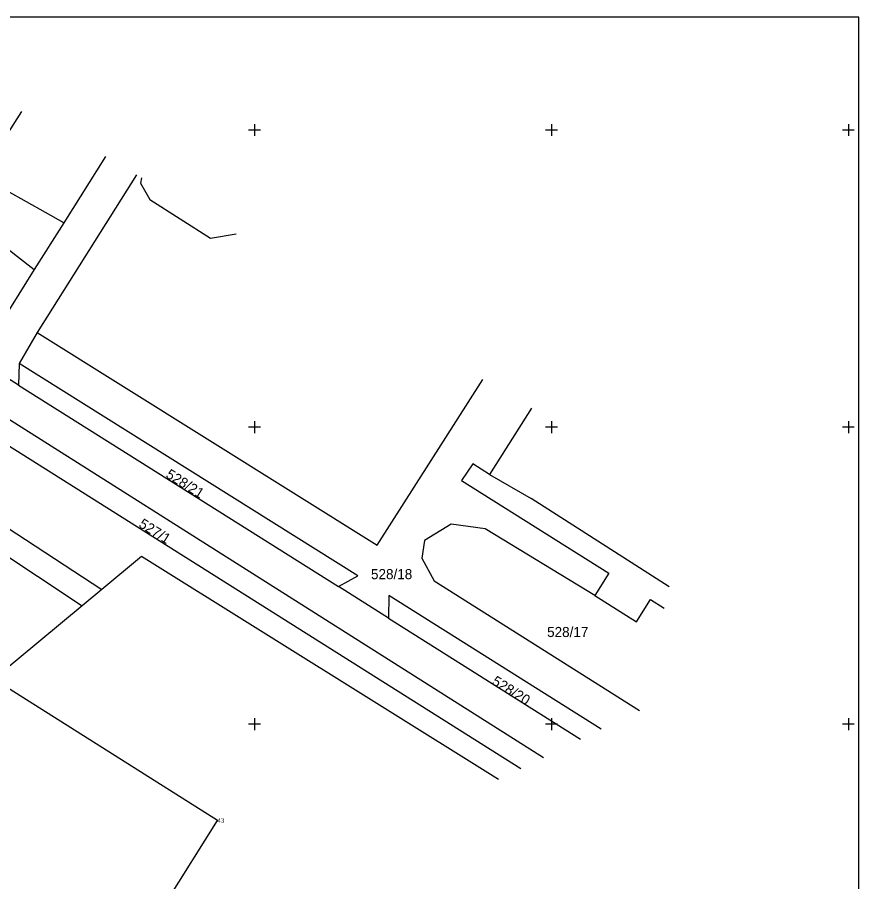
# Model space of a CAD drawing. Extents: x -645398 to -644998, y -1063322 to -1063031.
# Drawn here: x -645140 to -644998.3, y -1063176.5 to -1063031 of the extents above; entities that cross this region are included whole.
import ezdxf

# ---------------------------------------------------------------- set-up
doc = ezdxf.new("R2010")
doc.units = 0
for name, color, linetype in [('Bod', 7, 'Continuous'), ('Hranice KN pozemků', 7, 'Continuous'), ('Rámeček', 7, 'Continuous'), ('Souřadnicové křížky', 7, 'Continuous'), ('Stavby', 7, 'Continuous'), ('Vnitřní kresba parcel', 7, 'Continuous'), ('Čísla parcel', 7, 'Continuous'), ('Číslo bodu', 7, 'Continuous')]:
    doc.layers.add(name, color=color, linetype=linetype)

msp = doc.modelspace()

# ---------------------------------------------------------------- linework, layer by layer
at = {"layer": 'Bod'}
for q in [(-645106.29, -1063166.18), (-645106.29, -1063166.28), (-645106.19, -1063166.18), (-645106.19, -1063166.28)]:
    msp.add_line((-645106.24, -1063166.23), q, dxfattribs=at)
at = {"layer": 'Hranice KN pozemků'}
for p, q in [((-645146.11, -1063057.77), (-645139.21, -1063046.87)), ((-645119.88, -1063057.56), (-645136.61, -1063084.06)), ((-645136.61, -1063084.06), (-645139.63, -1063089.31)), ((-645139.74, -1063092.95), (-645148.3, -1063087.54)), ((-645139.63, -1063089.31), (-645139.74, -1063092.95)), ((-645139.74, -1063092.95), (-645085.88, -1063126.81)), ((-645119.02, -1063121.76), (-645125.74, -1063127.34)), ((-645058.94, -1063159.31), (-645119.02, -1063121.76)), ((-645125.74, -1063127.34), (-645129.04, -1063130.08)), ((-645077.42, -1063132.14), (-645085.88, -1063126.81)), ((-645129.04, -1063130.08), (-645143.96, -1063142.46)), ((-645077.42, -1063132.14), (-645045.1, -1063152.55))]:
    msp.add_line(p, q, dxfattribs=at)
for points in [[(-645236.73, -1063042.91), (-645233.9, -1063041.56), (-645230.85, -1063042.43), (-645219.03, -1063050.07), (-645152.72, -1063091.57), (-645140.39, -1063099.29), (-645051.35, -1063155.61)], [(-645236.73, -1063042.91), (-645154.72, -1063094.74), (-645140.39, -1063103.8), (-645055.15, -1063157.46)], [(-645125.1, -1063054.47), (-645132.12, -1063065.61), (-645135.23, -1063063.87), (-645141.6, -1063060.3), (-645146.11, -1063057.77)], [(-645119.05, -1063058.04), (-645119.23, -1063058.92), (-645117.65, -1063061.72)], [(-645117.65, -1063061.72), (-645107.4, -1063068.19), (-645103.09, -1063067.46)], [(-645149.78, -1063063.57), (-645139.91, -1063071.29), (-645137.09, -1063073.49), (-645144.94, -1063085.95), (-645148.3, -1063087.54)], [(-645136.61, -1063084.06), (-645079.35, -1063119.88), (-645061.53, -1063091.99)], [(-645085.88, -1063126.81), (-645082.63, -1063125.02), (-645139.63, -1063089.31)], [(-645053.34, -1063096.82), (-645060.41, -1063107.97), (-645063.26, -1063106.18), (-645065.12, -1063108.99), (-645040.36, -1063124.59), (-645042.69, -1063128.37)], [(-645186.47, -1063109.12), (-645179.53, -1063104.51), (-645170.44, -1063102.69), (-645159.02, -1063110.24), (-645129.04, -1063130.08)], [(-645042.69, -1063128.37), (-645061.17, -1063117.13), (-645066.86, -1063116.35), (-645071.4, -1063119.09), (-645071.84, -1063122.06), (-645069.75, -1063125.89)], [(-645069.75, -1063125.89), (-645035.16, -1063147.7)], [(-645041.62, -1063150.85), (-645077.39, -1063128.37), (-645077.42, -1063132.14)], [(-645042.69, -1063128.37), (-645035.7, -1063132.76), (-645033.33, -1063129), (-645031, -1063130.48)]]:
    msp.add_lwpolyline(points, dxfattribs=at)
at = {"layer": 'Rámeček'}
for p, q in [((-644998.25, -1063031.02), (-645398.25, -1063031.02)), ((-644998.25, -1063322.02), (-644998.25, -1063031.02))]:
    msp.add_line(p, q, dxfattribs=at)
at = {"layer": 'Souřadnicové křížky'}
for p, q in [((-645100, -1063049), (-645100, -1063051)), ((-645050, -1063049), (-645050, -1063051)), ((-645000, -1063049), (-645000, -1063051)), ((-645099, -1063050), (-645101, -1063050)), ((-645049, -1063050), (-645051, -1063050)), ((-644999, -1063050), (-645001, -1063050)), ((-645099, -1063100), (-645101, -1063100)), ((-645100, -1063099), (-645100, -1063101)), ((-645049, -1063100), (-645051, -1063100)), ((-645050, -1063099), (-645050, -1063101)), ((-644999, -1063100), (-645001, -1063100)), ((-645000, -1063099), (-645000, -1063101)), ((-645100, -1063149), (-645100, -1063151)), ((-645050, -1063149), (-645050, -1063151)), ((-645000, -1063149), (-645000, -1063151)), ((-645099, -1063150), (-645101, -1063150)), ((-645049, -1063150), (-645051, -1063150)), ((-644999, -1063150), (-645001, -1063150))]:
    msp.add_line(p, q, dxfattribs=at)
at = {"layer": 'Stavby'}
for p, q in [((-645106.24, -1063166.23), (-645177.05, -1063121.57)), ((-645183.59, -1063289.01), (-645106.24, -1063166.23))]:
    msp.add_line(p, q, dxfattribs=at)
at = {"layer": 'Vnitřní kresba parcel'}
for p, q in [((-645132.12, -1063065.61), (-645137.09, -1063073.49)), ((-645157.06, -1063106.79), (-645125.74, -1063127.34)), ((-645060.41, -1063107.97), (-645053.43, -1063112.02)), ((-645030.19, -1063126.88), (-645053.43, -1063112.02))]:
    msp.add_line(p, q, dxfattribs=at)

# ---------------------------------------------------------------- texts
at = {"layer": 'Čísla parcel'}
for s, p in [('528/21', (-645115.08, -1063108.39)), ('527/1', (-645119.63, -1063116.72)), ('528/20', (-645060.17, -1063143.2))]:
    msp.add_text(s, height=1.7, rotation=328, dxfattribs=at).set_placement(p)
for s, p in [('528/18', (-645080.39, -1063125.6)), ('528/17', (-645050.73, -1063135.34))]:
    msp.add_text(s, height=1.7, dxfattribs=at).set_placement(p)
at = {"layer": 'Číslo bodu'}
msp.add_text('43', height=0.75, dxfattribs=at).set_placement((-645106.24, -1063166.6))

doc.saveas('drawing.dxf')
